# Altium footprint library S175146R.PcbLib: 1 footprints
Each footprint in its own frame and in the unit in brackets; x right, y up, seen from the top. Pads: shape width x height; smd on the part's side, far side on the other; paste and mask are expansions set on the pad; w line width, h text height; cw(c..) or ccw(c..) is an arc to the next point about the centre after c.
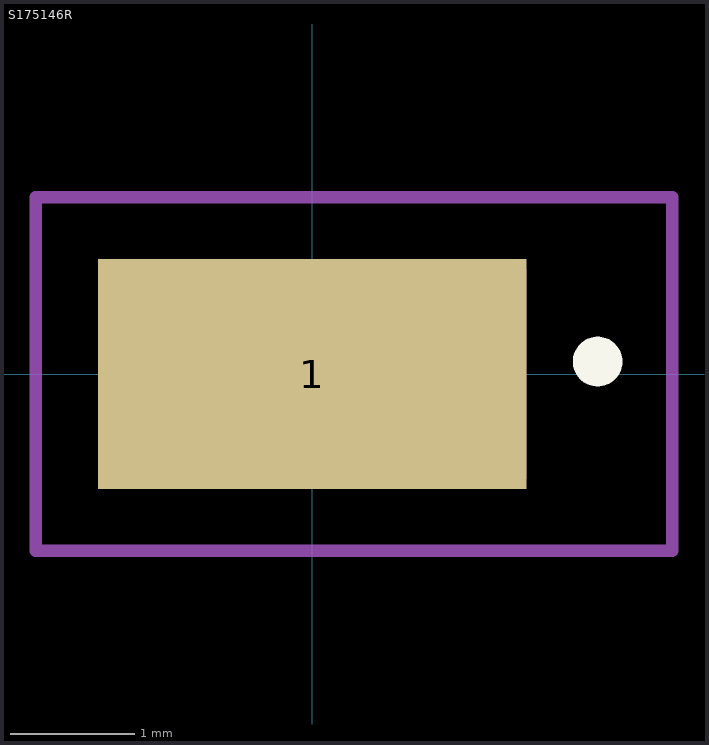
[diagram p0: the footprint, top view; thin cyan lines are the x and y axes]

## S175146R [mm]
pads (1):
  rect 3.45x1.85 smd: 1(0,0)
Top Overlay:
  lines w0.2: 2.3,0 cw(c2.3,0.1) 2.3,0.2 ; 2.3,0 2.3,0 ; 2.3,0 ccw(c2.3,0.1) 2.3,0.2 ; 2.3,0.2 2.3,0.2
Mechanical 15:
  lines w0.2: -1.625,-0.825 1.625,-0.825 1.625,0.825 -1.625,0.825 -1.625,-0.825
Mechanical 20:
  lines w0.1: -2.225,-1.425 2.9,-1.425 2.9,1.425 -2.225,1.425 -2.225,-1.425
